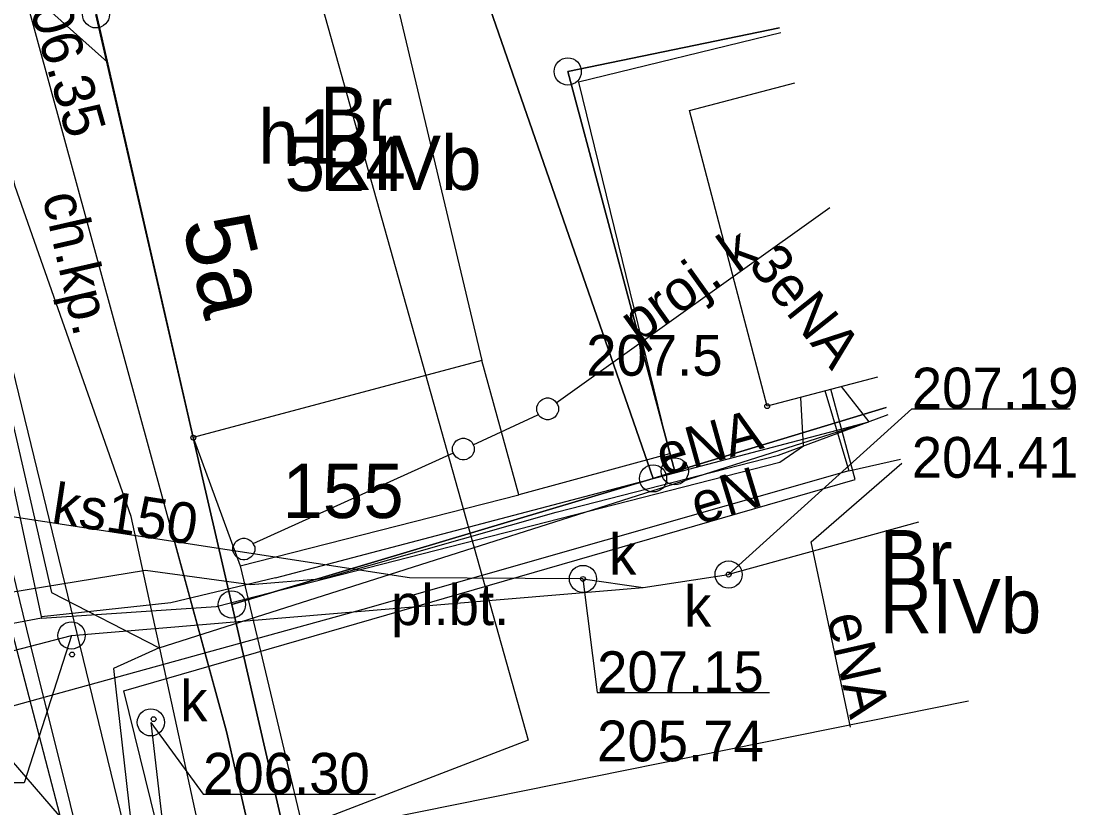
# Model space of a CAD drawing. Extents: x 6512400 to 6513200, y 6022500 to 6022750.
# Drawn here: x 6512865.8 to 6512885.21, y 6022580.12 to 6022594.6 of the extents above; entities that cross this region are included whole.
import ezdxf

# ---------------------------------------------------------------- set-up
doc = ezdxf.new("R2010")
doc.units = 0
for name, color, linetype in [('202-punkt graniczny', 7, 'Continuous'), ('203-punkt graniczny', 7, 'Continuous'), ('209-oznaczenie konturu klasyfikacyjnego', 7, 'Continuous'), ('210-oznaczenie konturu użytku gruntowego', 7, 'Continuous'), ('211-numer działki ewidencyjnej', 7, 'Continuous'), ('217-kontur klasyfikacyjny', 7, 'Continuous'), ('218-kontur użytku gruntowego', 7, 'Continuous'), ('219-działka ewidencyjna', 7, 'Continuous'), ('238-Punkt adresowy budynku', 7, 'Continuous'), ('312-budynek ewidencyjny', 7, 'Continuous'), ('312-oznaczenie budynku ewidencyjnego', 7, 'Continuous'), ('312-oznaczenie budynku ewidencyjnego-Atr117', 7, 'Continuous'), ('chodnik (powierzchnia)', 7, 'Continuous'), ('chodnik (powierzchnia)-Atr17', 7, 'Continuous'), ('inna obudowa przewodu - sieć gazowa (linia)', 7, 'Continuous'), ('krawężnik (linia)', 7, 'Continuous'), ('Obszar opracowania', 7, 'Continuous'), ('ogrodzenie trwałe (linia)', 7, 'Continuous'), ('plac (powierzchnia)', 7, 'Continuous'), ('plac (powierzchnia)-Atr17', 7, 'Continuous'), ('przewód elektroenergetyczny (linia)', 7, 'Continuous'), ('przewód elektroenergetyczny (linia)-Atr1', 7, 'Continuous'), ('przewód gazowy (linia)', 7, 'Continuous'), ('przewód kanalizacyjny (linia)', 7, 'Continuous'), ('przewód kanalizacyjny (linia)-Atr1', 7, 'Continuous'), ('przewód kanalizacyjny - projektowany lub w budowie (linia) - ob. projektowany', 7, 'Continuous'), ('przewód kanalizacyjny - projektowany lub w budowie (linia) - ob. projektowany-Atr1', 7, 'Continuous'), ('przewód wodociągowy (linia)', 7, 'Continuous'), ('punkt o określonej wysokości (sieć gazowa)-Atr2', 7, 'Continuous'), ('punkt o określonej wysokości (sieć kanalizacyjna)', 7, 'Continuous'), ('punkt o określonej wysokości (sieć kanalizacyjna)-Atr2', 7, 'Continuous'), ('punkt o określonej wysokości (sieć kanalizacyjna)-Atr3', 7, 'Continuous'), ('punkt wysokościowy naturalny', 7, 'Continuous'), ('punkt wysokościowy naturalny-Atr2', 7, 'Continuous'), ('urządzenie techniczne projektowane lub w budowie (sieć kanalizacyjna) - powierzchnia - ob. projektowany', 7, 'Continuous'), ('właz okrągły - siec kanalizacyjna (punkt)', 7, 'Continuous'), ('właz okrągły - siec kanalizacyjna (punkt)-Atr17', 7, 'Continuous')]:
    doc.layers.add(name, color=color, linetype=linetype)

# ---------------------------------------------------------------- blocks, each defined once
blk = doc.blocks.new('202')
blk.add_circle((0, 0), 0.25)
blk = doc.blocks.new('203')
blk.add_circle((0, 0), 0.045)
blk = doc.blocks.new('PW01')
blk.add_circle((0, 0), 0.045)
blk = doc.blocks.new('US22')
blk.add_circle((0, 0), 0.25)

msp = doc.modelspace()

# ---------------------------------------------------------------- linework, layer by layer
at = {"layer": '217-kontur klasyfikacyjny'}
for points in [[(6512873.92, 6022596.31), (6512877.43, 6022586.18)], [(6512877.43, 6022586.18), (6512873.92, 6022596.31)], [(6512867.18, 6022594.72), (6512868.97, 6022586.93)], [(6512875.86, 6022593.67), (6512879.756, 6022594.473)], [(6512879.756, 6022594.473), (6512875.86, 6022593.67)], [(6512877.83, 6022586.31), (6512875.86, 6022593.67)], [(6512875.86, 6022593.67), (6512877.83, 6022586.31)], [(6512877.83, 6022586.31), (6512881.718, 6022587.488)], [(6512881.718, 6022587.488), (6512877.83, 6022586.31)], [(6512868.97, 6022586.93), (6512869.68, 6022583.86)], [(6512877.43, 6022586.18), (6512877.83, 6022586.31)], [(6512877.83, 6022586.31), (6512877.43, 6022586.18)], [(6512869.68, 6022583.86), (6512877.43, 6022586.18)], [(6512877.43, 6022586.18), (6512869.68, 6022583.86)], [(6512869.68, 6022583.86), (6512872.457, 6022571.764)]]:
    msp.add_lwpolyline(points, dxfattribs=at)
at = {"layer": '218-kontur użytku gruntowego'}
for points in [[(6512873.92, 6022596.31), (6512877.43, 6022586.18)], [(6512877.43, 6022586.18), (6512873.92, 6022596.31)], [(6512867.18, 6022594.72), (6512868.97, 6022586.93)], [(6512868.97, 6022586.93), (6512867.18, 6022594.72)], [(6512875.86, 6022593.67), (6512879.756, 6022594.473)], [(6512879.756, 6022594.473), (6512875.86, 6022593.67)], [(6512877.83, 6022586.31), (6512875.86, 6022593.67)], [(6512875.86, 6022593.67), (6512877.83, 6022586.31)], [(6512877.83, 6022586.31), (6512881.718, 6022587.488)], [(6512881.718, 6022587.488), (6512877.83, 6022586.31)], [(6512868.97, 6022586.93), (6512869.68, 6022583.86)], [(6512869.68, 6022583.86), (6512868.97, 6022586.93)], [(6512877.43, 6022586.18), (6512877.83, 6022586.31)], [(6512877.83, 6022586.31), (6512877.43, 6022586.18)], [(6512869.68, 6022583.86), (6512877.43, 6022586.18)], [(6512877.43, 6022586.18), (6512869.68, 6022583.86)], [(6512869.68, 6022583.86), (6512872.457, 6022571.764)], [(6512872.457, 6022571.764), (6512869.68, 6022583.86)]]:
    msp.add_lwpolyline(points, dxfattribs=at)
at = {"layer": '219-działka ewidencyjna'}
for points in [[(6512873.92, 6022596.31), (6512877.43, 6022586.18)], [(6512867.18, 6022594.72), (6512868.97, 6022586.93)], [(6512879.756, 6022594.473), (6512875.86, 6022593.67)], [(6512875.86, 6022593.67), (6512877.83, 6022586.31)], [(6512881.718, 6022587.488), (6512877.83, 6022586.31)], [(6512868.97, 6022586.93), (6512869.68, 6022583.86)], [(6512877.43, 6022586.18), (6512877.83, 6022586.31)], [(6512869.68, 6022583.86), (6512877.43, 6022586.18)], [(6512872.457, 6022571.764), (6512869.68, 6022583.86)]]:
    msp.add_lwpolyline(points, dxfattribs=at)
at = {"layer": '312-budynek ewidencyjny'}
for points in [[(6512872.47, 6022595.97), (6512874.28, 6022588.35)], [(6512868.97, 6022586.93), (6512867.18, 6022594.72)], [(6512878.1, 6022592.95), (6512880.04, 6022593.462)], [(6512879.53, 6022587.51), (6512878.1, 6022592.95)], [(6512874.28, 6022588.35), (6512868.97, 6022586.93)], [(6512881.561, 6022588.046), (6512879.53, 6022587.51)], [(6512871.27, 6022579.67), (6512883.235, 6022582.085)]]:
    msp.add_lwpolyline(points, dxfattribs=at)
at = {"layer": 'chodnik (powierzchnia)'}
msp.add_lwpolyline([(6512866.67, 6022597.68), (6512867.17, 6022594.8), (6512868.97, 6022586.93)], dxfattribs=at)
at = {"layer": 'inna obudowa przewodu - sieć gazowa (linia)'}
msp.add_lwpolyline([(6512868.52, 6022585.4), (6512869.58, 6022581.52), (6512870.29, 6022578.43), (6512871.862, 6022571.535)], dxfattribs=at)
at = {"layer": 'krawężnik (linia)'}
msp.add_lwpolyline([(6512862.85, 6022595.89), (6512865.97, 6022583.13), (6512868.17, 6022574.3)], dxfattribs=at)
at = {"layer": 'Obszar opracowania'}
msp.add_lwpolyline([(6512710.98, 6022693.84), (6512748.35, 6022694.16), (6512798.11, 6022695.25), (6512807.47, 6022695.46), (6512809.66, 6022606.87), (6512863.71, 6022622.03), (6512875.13, 6022581.36), (6512755.22, 6022535.25), (6512691.61, 6022568.03), (6512709.16, 6022605.16)], close=True, dxfattribs=at)
at = {"layer": 'ogrodzenie trwałe (linia)'}
for points in [[(6512879.782, 6022594.381), (6512876.06, 6022593.47)], [(6512876.06, 6022593.47), (6512877.73, 6022586.63), (6512874.96, 6022585.88), (6512874.28, 6022588.35)]]:
    msp.add_lwpolyline(points, dxfattribs=at)
at = {"layer": 'plac (powierzchnia)'}
for points in [[(6512868.97, 6022586.93), (6512869.83, 6022584.57), (6512871.07, 6022579.37), (6512870.54, 6022578.14), (6512870.98, 6022575.93), (6512872, 6022576.2), (6512872.2, 6022575.31), (6512871.21, 6022575.06), (6512872.057, 6022571.61)], [(6512869.83, 6022584.57), (6512874.96, 6022585.88)]]:
    msp.add_lwpolyline(points, dxfattribs=at)
at = {"layer": 'przewód elektroenergetyczny (linia)'}
for points in [[(6512763.38, 6022676.06), (6512798.79, 6022676.04), (6512803.06, 6022673.02), (6512807.84, 6022668.96), (6512815.24, 6022662.53), (6512819.98, 6022657.77), (6512831.6, 6022645.79), (6512834.59, 6022642.25), (6512837.06, 6022638.75), (6512840.02, 6022634.13), (6512842.26, 6022630.04), (6512846.03, 6022621.35), (6512846.58, 6022618.9), (6512847.6, 6022616.23), (6512852.12, 6022605.09), (6512853.39, 6022601.13), (6512855.57, 6022592.48), (6512858.1, 6022582.86), (6512868.09, 6022584.49), (6512870.03, 6022584.23), (6512871.36, 6022584.34), (6512875.65, 6022585.56), (6512879.74, 6022586.61), (6512881.754, 6022587.357)], [(6512861.56, 6022603.29), (6512861.94, 6022603.39), (6512866.18, 6022583.61), (6512856.81, 6022581.85), (6512858.91, 6022573.95), (6512860.571, 6022567.194)], [(6512861.56, 6022603.29), (6512861.94, 6022603.39), (6512866.36, 6022584.08), (6512868.34, 6022583.06), (6512881.4, 6022587.22)], [(6512869.91, 6022577.24), (6512869.61, 6022577.28), (6512867.83, 6022585.48), (6512865.69, 6022591.55), (6512863.34, 6022601.78), (6512862.79, 6022603.03), (6512861.56, 6022603.29)], [(6512852.76, 6022570.72), (6512852.4, 6022572.17), (6512858.48, 6022574.45), (6512869.09, 6022576.59), (6512867.69, 6022582.27), (6512881.15, 6022586.16), (6512880.7, 6022587.82)], [(6512880.59, 6022587.8), (6512881.03, 6022586.32), (6512881.985, 6022586.535)], [(6512880.89, 6022587.87), (6512881.4, 6022587.22)], [(6512866.19, 6022583.6), (6512866.18, 6022583.61), (6512869.39, 6022583.82), (6512879.76, 6022586.48), (6512880.2, 6022586.78), (6512880.15, 6022587.67)], [(6512870.48, 6022584.35), (6512881.4, 6022587.22)], [(6512881.06, 6022581.6), (6512880.34, 6022585.01), (6512882.007, 6022586.458)], [(6512881.03, 6022586.32), (6512872.09, 6022583.77), (6512862.68, 6022581.17), (6512856.97, 6022579.46), (6512860.103, 6022567.013)], [(6512870.48, 6022584.35), (6512868.56, 6022583.89), (6512866.18, 6022583.63)], [(6512866.18, 6022583.61), (6512856.81, 6022581.85), (6512858.91, 6022573.95), (6512860.571, 6022567.194)], [(6512868.34, 6022583.06), (6512867.5, 6022582.68)], [(6512867.5, 6022582.68), (6512868.37, 6022575.03), (6512869.514, 6022570.632)]]:
    msp.add_lwpolyline(points, dxfattribs=at)
at = {"layer": 'przewód gazowy (linia)'}
msp.add_lwpolyline([(6512871.862, 6022571.535), (6512870.29, 6022578.43), (6512869.58, 6022581.52), (6512865.64, 6022595.96), (6512860.06, 6022617.51), (6512858.39, 6022625.33), (6512855.49, 6022634.19), (6512854.83, 6022641.62)], dxfattribs=at)
at = {"layer": 'przewód kanalizacyjny (linia)'}
for points in [[(6512861.99, 6022598.66), (6512867.39, 6022593.84)], [(6512861.16, 6022586.16), (6512870.65, 6022575.16)], [(6512876.14, 6022584.33), (6512872.95, 6022584.35), (6512861.16, 6022586.16)], [(6512882.312, 6022585.372), (6512878.82, 6022584.41)], [(6512866.73, 6022583.29), (6512877.25, 6022584.17), (6512878.82, 6022584.41)], [(6512876.14, 6022584.33), (6512877.25, 6022584.17)], [(6512840.49, 6022576.47), (6512866.73, 6022583.29)], [(6512868.19, 6022581.69), (6512868.88, 6022575.69)]]:
    msp.add_lwpolyline(points, dxfattribs=at)
at = {"layer": 'przewód kanalizacyjny - projektowany lub w budowie (linia) - ob. projektowany'}
for points in [[(6512875.65, 6022587.57), (6512880.685, 6022591.165)], [(6512874.12, 6022586.8), (6512875.31, 6022587.35)], [(6512870.07, 6022584.98), (6512873.76, 6022586.65)]]:
    msp.add_lwpolyline(points, dxfattribs=at)
at = {"layer": 'przewód wodociągowy (linia)'}
for points in [[(6512869.887, 6022570.776), (6512864.23, 6022594.01), (6512863.79, 6022596.02), (6512861.84, 6022602.88)], [(6512869.005, 6022570.437), (6512862.93, 6022593.72)]]:
    msp.add_lwpolyline(points, dxfattribs=at)
at = {"layer": 'punkt o określonej wysokości (sieć kanalizacyjna)-Atr2'}
for points in [[(6512878.82, 6022584.41), (6512882.19, 6022587.46), (6512885.102, 6022587.46)], [(6512876.14, 6022584.33), (6512876.4, 6022582.24), (6512879.573, 6022582.24)], [(6512866.73, 6022583.29), (6512865.86, 6022580.58), (6512862.719, 6022580.58)], [(6512868.19, 6022581.69), (6512869.15, 6022580.37), (6512872.323, 6022580.37)]]:
    msp.add_lwpolyline(points, dxfattribs=at)
at = {"layer": 'urządzenie techniczne projektowane lub w budowie (sieć kanalizacyjna) - powierzchnia - ob. projektowany'}
for points in [[(6512875.69, 6022587.46), (6512875.69, 6022587.42), (6512875.67, 6022587.38), (6512875.65, 6022587.34), (6512875.62, 6022587.31), (6512875.59, 6022587.29), (6512875.55, 6022587.27), (6512875.51, 6022587.26), (6512875.47, 6022587.26), (6512875.43, 6022587.27), (6512875.39, 6022587.29), (6512875.36, 6022587.31), (6512875.33, 6022587.34), (6512875.31, 6022587.38), (6512875.29, 6022587.42), (6512875.29, 6022587.46), (6512875.29, 6022587.5), (6512875.31, 6022587.54), (6512875.33, 6022587.58), (6512875.36, 6022587.61), (6512875.39, 6022587.63), (6512875.43, 6022587.65), (6512875.47, 6022587.66), (6512875.51, 6022587.66), (6512875.55, 6022587.65), (6512875.59, 6022587.63), (6512875.62, 6022587.61), (6512875.65, 6022587.58), (6512875.67, 6022587.54), (6512875.69, 6022587.5)], [(6512874.14, 6022586.72), (6512874.14, 6022586.68), (6512874.12, 6022586.64), (6512874.1, 6022586.6), (6512874.07, 6022586.57), (6512874.04, 6022586.55), (6512874, 6022586.53), (6512873.96, 6022586.52), (6512873.92, 6022586.52), (6512873.88, 6022586.53), (6512873.84, 6022586.55), (6512873.81, 6022586.57), (6512873.78, 6022586.6), (6512873.76, 6022586.64), (6512873.74, 6022586.68), (6512873.74, 6022586.72), (6512873.74, 6022586.76), (6512873.76, 6022586.8), (6512873.78, 6022586.84), (6512873.81, 6022586.87), (6512873.84, 6022586.89), (6512873.88, 6022586.91), (6512873.92, 6022586.92), (6512873.96, 6022586.92), (6512874, 6022586.91), (6512874.04, 6022586.89), (6512874.07, 6022586.87), (6512874.1, 6022586.84), (6512874.12, 6022586.8), (6512874.14, 6022586.76)], [(6512870.1, 6022584.88), (6512870.1, 6022584.84), (6512870.08, 6022584.8), (6512870.06, 6022584.76), (6512870.03, 6022584.73), (6512870, 6022584.71), (6512869.96, 6022584.69), (6512869.92, 6022584.68), (6512869.88, 6022584.68), (6512869.84, 6022584.69), (6512869.8, 6022584.71), (6512869.77, 6022584.73), (6512869.74, 6022584.76), (6512869.72, 6022584.8), (6512869.7, 6022584.84), (6512869.7, 6022584.88), (6512869.7, 6022584.92), (6512869.72, 6022584.96), (6512869.74, 6022585), (6512869.77, 6022585.03), (6512869.8, 6022585.05), (6512869.84, 6022585.07), (6512869.88, 6022585.08), (6512869.92, 6022585.08), (6512869.96, 6022585.07), (6512870, 6022585.05), (6512870.03, 6022585.03), (6512870.06, 6022585), (6512870.08, 6022584.96), (6512870.1, 6022584.92)]]:
    msp.add_lwpolyline(points, close=True, dxfattribs=at)

# ---------------------------------------------------------------- block references
at = {"layer": '202-punkt graniczny'}
for p in [(6512867.18, 6022594.72), (6512875.86, 6022593.67), (6512877.83, 6022586.31), (6512877.43, 6022586.18), (6512869.68, 6022583.86)]:
    msp.add_blockref('202', p, dxfattribs=at)
at = {"layer": '203-punkt graniczny'}
msp.add_blockref('203', (6512868.97, 6022586.93), dxfattribs=at)
at = {"layer": 'punkt o określonej wysokości (sieć kanalizacyjna)'}
for p in [(6512876.14, 6022584.33), (6512878.82, 6022584.41), (6512866.74, 6022582.94), (6512868.24, 6022581.75)]:
    msp.add_blockref('PW01', p, dxfattribs=at)
at = {"layer": 'punkt wysokościowy naturalny'}
msp.add_blockref('PW01', (6512879.53, 6022587.51), dxfattribs=at)
at = {"layer": 'właz okrągły - siec kanalizacyjna (punkt)'}
for p in [(6512876.14, 6022584.33), (6512878.82, 6022584.41), (6512866.73, 6022583.29), (6512868.19, 6022581.69)]:
    msp.add_blockref('US22', p, dxfattribs=at)

# ---------------------------------------------------------------- texts
at = {"layer": '209-oznaczenie konturu klasyfikacyjnego'}
for p in [(6512871.3, 6022591.49), (6512881.6, 6022583.33)]:
    msp.add_text('RIVb', height=1, dxfattribs=at).set_placement(p)
at = {"layer": '210-oznaczenie konturu użytku gruntowego'}
for p in [(6512871.3, 6022592.39), (6512881.6, 6022584.23)]:
    msp.add_text('Br', height=1, dxfattribs=at).set_placement(p)
at = {"layer": '211-numer działki ewidencyjnej'}
msp.add_text('155', height=1, dxfattribs=at).set_placement((6512870.61, 6022585.45))
at = {"layer": '238-Punkt adresowy budynku'}
msp.add_text('5a', height=1.25, rotation=283.454, dxfattribs=at).set_placement((6512868.76, 6022590.88))
at = {"layer": '312-oznaczenie budynku ewidencyjnego'}
msp.add_text('524', height=1, dxfattribs=at).set_placement((6512870.65, 6022591.47))
at = {"layer": '312-oznaczenie budynku ewidencyjnego-Atr117'}
msp.add_text('h1', height=1, dxfattribs=at).set_placement((6512870.166, 6022591.97))
at = {"layer": 'chodnik (powierzchnia)-Atr17'}
msp.add_text('ch.kp.', height=0.75, rotation=282.882, dxfattribs=at).set_placement((6512866.19, 6022591.37))
at = {"layer": 'plac (powierzchnia)-Atr17'}
msp.add_text('pl.bt.', height=0.75, dxfattribs=at).set_placement((6512872.61, 6022583.48))
at = {"layer": 'przewód elektroenergetyczny (linia)-Atr1'}
for s, rotation, p in [('3eNA', 308.525, (6512879.16, 6022590.11)), ('eNA', 15.527, (6512877.61, 6022586.22)), ('eN', 16.922, (6512878.26, 6022585.32)), ('eNA', 282.748, (6512880.63, 6022583.63))]:
    msp.add_text(s, height=0.75, rotation=rotation, dxfattribs=at).set_placement(p)
at = {"layer": 'przewód kanalizacyjny (linia)-Atr1'}
msp.add_text('ks150', height=0.75, rotation=351.272, dxfattribs=at).set_placement((6512866.34, 6022585.36))
at = {"layer": 'przewód kanalizacyjny - projektowany lub w budowie (linia) - ob. projektowany-Atr1'}
msp.add_text('proj. k', height=0.75, rotation=35.523, dxfattribs=at).set_placement((6512877.16, 6022588.65))
at = {"layer": 'punkt o określonej wysokości (sieć gazowa)-Atr2'}
msp.add_text('206.35', height=0.75, rotation=286.066, dxfattribs=at).set_placement((6512865.81, 6022595.35))
at = {"layer": 'punkt o określonej wysokości (sieć kanalizacyjna)-Atr2'}
for s, p in [('207.19', (6512882.19, 6022587.468)), ('207.15', (6512876.4, 6022582.248)), ('206.30', (6512869.15, 6022580.378))]:
    msp.add_text(s, height=0.75, dxfattribs=at).set_placement(p)
at = {"layer": 'punkt o określonej wysokości (sieć kanalizacyjna)-Atr3'}
for s, p in [('204.41', (6512882.19, 6022586.192)), ('205.74', (6512876.4, 6022580.973))]:
    msp.add_text(s, height=0.75, dxfattribs=at).set_placement(p)
at = {"layer": 'punkt wysokościowy naturalny-Atr2'}
msp.add_text('207.5', height=0.75, dxfattribs=at).set_placement((6512876.2, 6022588.07))
at = {"layer": 'właz okrągły - siec kanalizacyjna (punkt)-Atr17'}
for p in [(6512876.62, 6022584.41), (6512878, 6022583.45), (6512868.73, 6022581.71)]:
    msp.add_text('k', height=0.75, dxfattribs=at).set_placement(p)

doc.saveas('drawing.dxf')
